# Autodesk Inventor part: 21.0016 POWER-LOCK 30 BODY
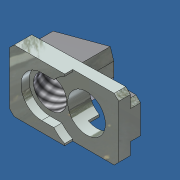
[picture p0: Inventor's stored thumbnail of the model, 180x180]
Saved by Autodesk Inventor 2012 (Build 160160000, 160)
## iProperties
Created: 2015-06
Part Number: 21.0016 POWER-LOCK 30 BODY
Material: Steel
Document SubType Name: Modeling
Designer: Admin
Density: 7.85 g/cm^3
Mass: 7.95848 g
Surface Area: 12.7833 cm^2
Volume: 1.01382 cm^3
Author: Admin
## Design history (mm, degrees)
feature "Base1"
body "Solid1"
